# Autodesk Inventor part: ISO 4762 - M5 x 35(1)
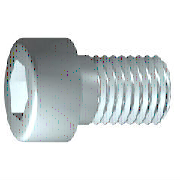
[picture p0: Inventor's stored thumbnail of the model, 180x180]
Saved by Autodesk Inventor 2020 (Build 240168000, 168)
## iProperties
Created: 2019-01
Part Number: ISO 4762 - M5 x 35(1)
Material: Nerezová ocel 440C
Description: Šroub s válcovou hlavou s vnitřním šestihranem
Document SubType Name: Modeling
Standard: ISO 4762
Designer: doma
Standard Revision: Fourth edition 2004-03-01
Standards Organization: ISO
Language: cs-CZ
Size Designation: M5 x 35
Categories: <MemberInstance><Categories><Category DisplayName="Spojovací materiál" InternalName="e4da775c-781d-43d5-af7c-5136215cf5a6" Mnemonic="FSTN"><Category DisplayName
Density: 7.75 g/cm^3
Appearance: Pololeštěná
IsCustomPart: 0
Author: doma
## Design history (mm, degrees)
sketch "Náčrt1"
  geometry: L1 (-1.167, 0)-(35, 0); L2 (35, 0)-(35, 2.5); L3 (35, 2.5)-(13, 2.5); L4 (13, 2.5)-(12.509, 2.5); L5 (12.509, 2.5)-(0, 2.5); L6 (0, 2.5)-(0, 4.25); L7 (0, 4.25)-(-5, 4.25); L8 (-5, 4.25)-(-5, 2.309); L9 (-5, 2.309)-(-2.5, 2.309); L10 (-2.5, 2.309)-(-1.167, 0); L11 (-13, 0)-(43, 0) reference; L12 (0, -0.85)-(0, 5.1) reference; L13 (13, 2.5)-(0, 2.5)
  constraints: 22 end point, 6 parallel, 2 collinear, 2 perpendicular, 1 horizontal, 1 point on line
  dimensions: "d1" = 22 distance from line of L3.end L2 (= GEL); "d2" = 0.49086 distance of L4.end L3.end (computed from GAL); "d3" = 5 distance between parallel lines of L8 L6 (= KOH); "d4" = 2.5 distance of L8.end L9.end (= INTI); "d5" = 60 deg angle of L10 L1; "d6" = 5 diameter of L3 L1 (= GD); "d7" = 5 diameter of L5 L1 (= BDM); "d8" = 4.6188 diameter of L9 L1 (= 1.1547 x SW); "d9" = 8.5 diameter of L7 L1 (= KOD); "d26" = 35 distance between parallel lines of L12 L2 (= NLG)
revolve "Těleso" sketch "Náčrt1" stored, may be unused: angle "d10" = 90 deg
sketch "Náčrt2"
  geometry: L1 (0, -5.95)-(0, 5.95) reference; L2 (-5.95, 0)-(5.95, 0) reference; L3 (2.309, 0)-(1.155, -2); L4 (1.155, -2)-(-1.155, -2); L5 (-1.155, -2)-(-2.309, 0); L6 (-2.309, 0)-(-1.155, 2); L7 (-1.155, 2)-(1.155, 2); L8 (1.155, 2)-(2.309, 0); 2 further points
  constraints: 12 end point, 1 coincident, 1 horizontal alignment, 1 point on line, 12 other
extrude "Drážka" join sketch "Náčrt2" stored distance "d11" = 10; taper "d12" = 0 deg
workplane "Work Plane1"
fillet "Fillet2" dims "d30" = 0.1 (= R)
body "Solid1"
fillet "Zaoblení1" dims "d17" = 0.5 (= RR)
feature "Závit" dims "d13" = 22 (= GEL), "d14" = 0
chamfer "Zkosení1" distance "d15" = 0.49076 (= -0.5 x SPD + 0.5 x GD); stored, may be unused: second distance "d16" = 0.49076 (= GUL), angle "d27" = 45 deg
other parameters: "GD" = 5 [user parameter; used in 2 equation terms], "NLG" = 35 [user parameter; used in 1 equation term], "GEL" = 22 [user parameter; used in 2 equation terms], "KOD" = 8.5 [user parameter; used in 1 equation term], "KOH" = 5 [user parameter; used in 1 equation term], "INTI" = 2.5 [user parameter; used in 1 equation term], "GAL" = 0.49076 (= 0.61345 x PTC) [user parameter; used in 1 equation term], "GUL" = 0.49076 (= 0.61345 x PTC) [user parameter; used in 1 equation term], "BDM" = 5 (= NND) [user parameter; used in 1 equation term], "SW" = 4 [user parameter; used in 2 equation terms], "RR" = 0.5 [user parameter; used in 1 equation term], "SPD" = 4.01848 (= NND - 1.2269 x PTC) [user parameter; used in 1 equation term], "d19" = 0, "d28" = 0, "d29" = 0, "R" = 0.1 [user parameter; used in 1 equation term], "TOA" = 30 deg [user parameter], "GD1" = 4.01848 (= THREADDIA - 1.2269 x PTC) [user parameter], "THREADDIA" = 5 [user parameter; used in 1 equation term], "FAWI" = 45 deg [user parameter], "TPU" = 12.5 (computed from PTC) [user parameter], "PTC" = 0.8 [user parameter; used in 5 equation terms], "NND" = 5 [user parameter; used in 2 equation terms], "E0" = 4.62 (= 1.155 x SW) [user parameter]
